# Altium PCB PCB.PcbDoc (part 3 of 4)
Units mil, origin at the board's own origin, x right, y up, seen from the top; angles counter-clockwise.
Board outline 6311.26 x 4737.49 mil, 2 copper layers (Top Layer, Bottom Layer); 252 components, 238 nets, 1140 pads, 635 vias.
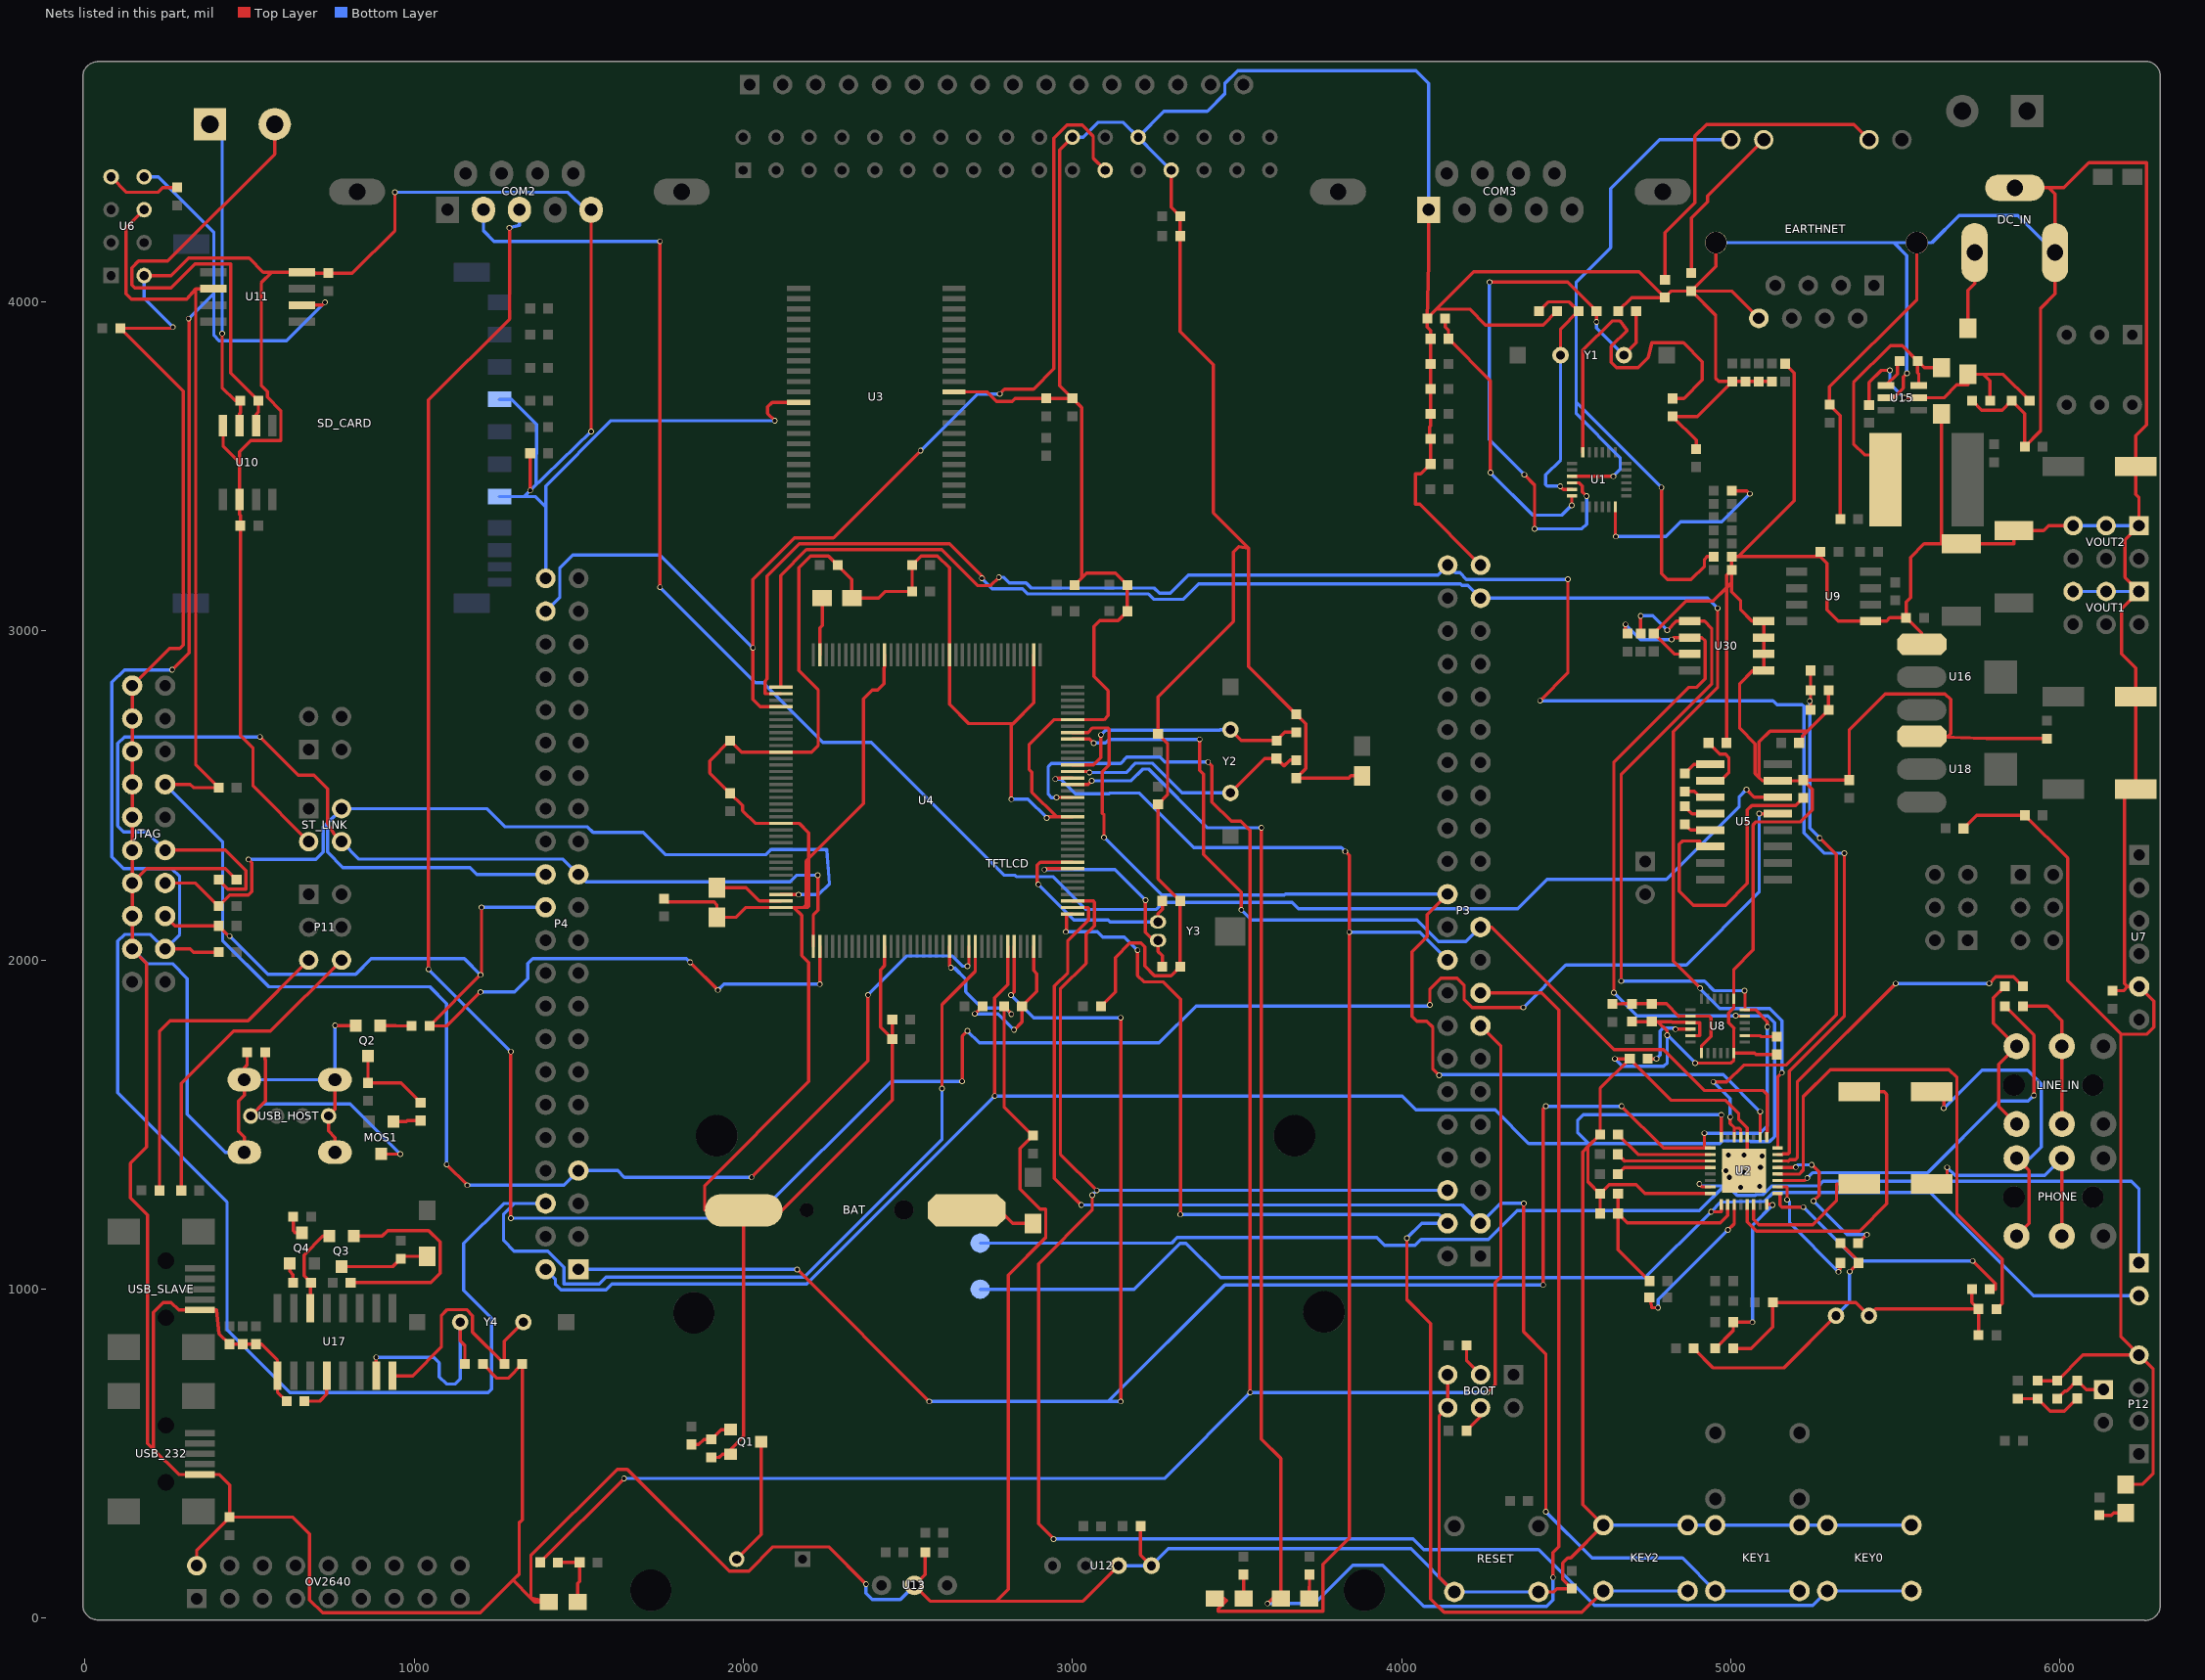
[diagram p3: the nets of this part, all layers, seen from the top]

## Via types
v1: diameter 17, hole 12, Top Layer to Bottom Layer, 622 vias
v2: diameter 25, hole 15, Top Layer to Bottom Layer, 9 vias
v3: diameter 275.59, hole 129.92, Top Layer to Bottom Layer, 4 vias

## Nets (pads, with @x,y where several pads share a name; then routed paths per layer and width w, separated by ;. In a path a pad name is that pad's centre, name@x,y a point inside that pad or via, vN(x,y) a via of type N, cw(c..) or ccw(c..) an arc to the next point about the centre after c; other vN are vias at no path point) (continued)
GND: 94.1 BAT.2 BOOT.5 BOOT.6 C3.1 C5.1 C7.1 C8.1 C11.1 C12.1 C13.1 C14.1 C15.1 C22.1 C23.1 C27.1 C28.1 C29.1 C30.1 C31.1 C32.1 C33.1 C34.1 C35.1 C36.1 C37.1 C38.2 C39.2 C40.2 C41.1 C42.1 C43.2 C44.2 C45.2 C46.1 C47.1 C48.1 C49.1 C50.1 C51.1 C52.1 C53.1 C54.1 C55.1 C56.1 C57.1 C58.1 C59.1 C60.1 C61.1 C62.1 C63.2 C65.2 C66.1 C68.1 C69.1 C70.2 C71.2 C72.1 C73.1 C74.1 C75.2 C76.1 C77.1 C78.2 C79.1 C80.1 C81.2 C82.1 C84.1 C85.2 C86.1 C87.2 C88.2 C89.1 C90.1 C91.1 C92.1 C93.1 C95.1 C96.2 C97.1 C98.1 C99.1 COM2.5 COM3.1 D3.1 D5.1 D6.1 DC_IN.2 DC_IN.3 EARTHNET.8 EARTHNET.13 EARTHNET.14 JTAG.4 JTAG.6 JTAG.8 JTAG.10 JTAG.12 JTAG.14 JTAG.16 JTAG.18 JTAG.20 KEY0.1 KEY1.1 KEY2.1 LS.1 OV2640.2 P3.43 P4.44 P12.4 PWR.2 Q1.1 Q2.1 R8.2 R9.2 R10.1 R11.1 R15.1 R17.1 R18.1 R19.1 R26.2 R36.1 R40.2 R61.1 R67.2 RESET.2 SD_CARD.3 SD_CARD.6 ST_LINK.3 TFTLCD.22 TFTLCD.26 TFTLCD.27 U2.12 U2.24 U2.33 U3.12 U3.34 U4.16 U4.31 U4.38 U4.51 U4.61 U4.83 U4.94 U4.107 U4.120 U4.130 U5.15 U6.1 U7.5 U8.1 U8.9 U8.11 U8.18 U9.5 U10.2 U10.8 U11.4 U12.3 U12.4 U13.2 U15.2 U16.1 U17.1 U18.1 U30.1 U30.2 U30.3 U30.4 U30.7 USB_232.5 USB_HOST.4 USB_HOST.5 USB_HOST.6 USB_HOST.7 USB_HOST.8 USB_SLAVE.5 VOUT1.1 VOUT1.3 VOUT1.5 VOUT2.1 VOUT2.3 VOUT2.5 | length 66976.9
  Top Layer w9.84: 4739.39,1291.1 U2.24@4937.59,1291.1 ; 4821.58,1811.58 4869.1,1811.58 4869.1,1809.84 U8.9@4877.28,1809.84 4906,1809.84 4906,1770.47 U8.11@4877.28,1770.47 ; v1(4891.79,1687.21) 5000.42,1687.21 5009.21,1696 U8.18@5009.21,1717.28 5009.21,1793.79 ; 4993.5,1840 5009.21,1855.71 U8.1@5009.21,1882.72 5009.21,1972 ; 5023.72,1516.28 5049.84,1490.16 U2.12@5049.84,1462.41 U2.33@5049.84,1369.84
  Top Layer w10: U6.1@180,4080 262,4080 315,4133 499.06,4133 542,4090.06 568,4090.06 ; v1(267.56,3923.44) 264.06,3919.94 C70.2@107.5,3919.94 298.5,3728.94 298.5,2957.5 288,2947 257,2947 JTAG.20@144,2834 JTAG.18@144,2734 JTAG.16@144,2634 JTAG.14@144,2534 JTAG.12@144,2434 JTAG.10@144,2334 JTAG.8@144,2234 ; OV2640.2@340,160 340,207.44 C65.2@440.06,307.5 ; U10.8@420,3624.41 420,3562 470,3512 ; R36.1@461,2244 427,2278 188,2278 JTAG.8@144,2234 ; USB_HOST.8@484.41,1416.06 484.41,1462.59 467,1480 467,1572.59 484.41,1590 USB_HOST.7@484.41,1636.54 484.41,1673 493,1681.59 C80.1@493,1720 ; C93.1@613,660 585,688 U17.1@585,737.64 585,785 537,833 C92.1@520,833 C91.1@480,833 C97.1@440,833 408,865 400,937.01 USB_SLAVE.5@349.06,937.01 285,937.01 262.01,960 238.01,960 208,929.99 208,514.01 ; ST_LINK.3@680,2360 511,2529 511,2644 472.5,2682.5 C75.2@472.5,3320.06 472.5,3351.06 470,3353.56 U10.2@470,3400 470,3512 ; USB_HOST.5@760,1416.06 760,1461 740.31,1480.69 USB_HOST.4@740.31,1526.3 760,1545.99 USB_HOST.6@760,1636.54 ; v1(760,1801.26) Q2.1@822.6,1801.26 ; v1(942,4333) 942,4217 812.5,4087.5 C78.2@740.06,4087.5 700.56,4087.5 698,4090.06 U11.4@660,4090.06 568,4090.06 ; C98.1@1209,773 1252.3,729.7 1285.7,729.7 C99.1@1329,773 1329,299.5 1319.5,290 1319.5,134.5 1301,116 ; v1(1353,3427) C72.1@1353,3540 ; v1(1538,3606) COM2.5@1538,4280 ; C57.1@1760,2187 1770.5,2176.5 1911.44,2176.5 1919.94,2168 C45.2@1919.94,2130 1977,2130 2006.66,2159.66 U4.107@2114.53,2159.66 2154.34,2159.66 ; R61.1@1903,489 1927,489 1936.6,498.6 Q1.1@1961.74,498.6 1961.74,514 2001.48,553.74 BAT.2@2001.48,1240 ; v1(2096,3639) 2074,3661 2074,3680.94 2088,3694.94 U3.34@2167.91,3694.94 ; v1(2373,104) 2260,217 2090.62,217 2017,143.38 1957.62,143.38 1648,453 1617,453 1355,191 1355,62 ; U4.120@2429.49,2041.55 2429.49,1982.95 2417.04,1970.5 2417.04,1795.96 C58.1@2453,1760 ; U4.61@2429.49,2927.38 2429.49,2890 2427.67,2888.18 2427.67,2840 2408.67,2821 2392,2821 2365,2794 2365,2475 2198.72,2308.72 ; C59.1@2453,1820 C58.1@2453,1760 ; C82.1@2553,200 2553,133 U13.2@2520,100 2568,52 2769,52 ; U4.130@2626.34,2041.55 2626.34,1981.66 v1(2631,1977) ; U3.12@2640.35,3726.43 2741.63,3726.43 2770,3698.06 2816.73,3698.06 2825.67,3707 C36.1@2920,3707 C37.1@3000,3707 ; v1(2814.44,1835.89) 2814.44,1838.13 R26.2@2792.5,1860.06 2792.5,1554.5 C61.1@2880,1467 2841,1428 2841,1304 2902,1243 2919,1243 2919,1157 2805,1043 2805,88 2769,52 ; v1(2814.5,2489) 2814.5,2713.5 2819.71,2718.71 ; U4.38@2882.24,2927.38 2882.24,2781.24 2819.71,2718.71 ; v1(2922,2432) 2925.25,2435.25 2952,2435.25 ; TFTLCD.22@2999.92,4500.24 2961.58,4461.89 2961.58,3745.42 C37.1@3000,3707 ; U4.16@3000.35,2435.25 2952,2435.25 ; C52.1@3007,3140 3028,3161 ; C60.1@3087,1860 3130.5,1903.5 3130.5,2008 3174,2051.5 3208,2051.5 3219.5,2040 3219.5,1981.5 3249,1952 3299.56,1952 C40.2@3327.5,1979.94 C43.2@3327.5,2179.94 3260,2247.44 C50.1@3260,2473 3289,2502 3289,2658 C49.1@3260,2687 3260,2800.28 3489,3029.28 3489,3240 3505,3256 3535.5,3251.75 ; U12.3@3140,160 3032,52 2769,52 ; C79.1@3207,280 3207,193 U12.4@3240,160 ; TFTLCD.27@3299.92,4400.24 3299.92,4287.51 C38.2@3327.5,4259.94 C39.2@3327.5,4199.94 3327.5,3909.5 3428,3809 3428,3359.25 3535.5,3251.75 ; C62.1@3880.06,2560 3846.46,2560 3839.46,2553 C42.1@3680,2553 3709,2582 3709,2718 C41.1@3680,2747 3535.5,2891.5 3535.5,3251.75 ; COM3.1@4082,4280 4082,4119 C12.1@4078,3950 ; BOOT.5@4140,740 BOOT.6@4140,640 4114,614 4114,126 RESET.2@4160,80 ; P3.43@4240,3200 4054.94,3385.06 4041.5,3385.06 4041.5,3477.06 4057.81,3477.06 C28.1@4088,3507.25 C27.1@4088,3583.38 4085.36,3586.02 4085.36,3621 4088,3623.64 C15.1@4088,3659.5 C14.1@4088,3735.63 C13.1@4088,3811.75 C11.1@4088,3887.88 4088,3913 4078,3923 C12.1@4078,3950 ; RESET.2@4415.91,80 4461,80 4471,90 C48.1@4517,90 4489,118 4489,168 4505,184 4514,184 KEY2.1@4613,283 4550,346 4550,1417 4566,1433 ; C23.1@4472,3972 4430,3930 4255,3930 4207,3978 4106,3978 ; C3.1@4603,1230 C5.1@4603,1290 ; v1(4648,1700) C77.1@4693,1700 ; C22.1@4658,3972 4699,4013 R18.1@4800,4013 ; C73.1@4700,1813 C74.1@4760,1813 4778,1813 ; 4739.39,1291.1 4712.5,1318 4631,1318 C5.1@4603,1290 ; v1(4807,1772) 4807,1784 4778,1813 ; 4821.58,1811.58 4820.16,1813 4778,1813 ; U30.7@4875.59,2930 4828.56,2930 C81.2@4766.06,2992.5 4864.5,3090.94 4945.94,3090.94 4987,3132 ; R10.1@4895,3553 4895,3580 R11.1@4823,3652 4898.94,3652 C33.1@5004.94,3758 ; EARTHNET.14@4954.88,4180 4954.88,4107.88 R19.1@4880,4033 ; C66.1@4987,2660 4987,3132 ; 4993.5,1840 4993.5,1809.5 5009.21,1793.79 ; U8.18@5009.21,1717.28 5072,1717.28 5076.28,1713 C76.1@5140,1713 ; 5009.21,1972 5068,2030.79 5068,2411 5077,2420 5212,2420 5248,2456 5248,2519 C68.1@5220,2547 ; 5023.72,1516.28 5023.72,1534.28 4984,1574 4819,1574 C77.1@4693,1700 ; U2.33@5040,1360 U2.33@5049.84,1369.84 ; EARTHNET.8@5085.2,3950 5002.2,4033 R19.1@4880,4033 ; C30.1@5124.94,3758 C31.1@5084.94,3758 C32.1@5044.94,3758 C33.1@5004.94,3758 ; C29.1@5164.94,3812 5192.87,3784.06 5192.87,3395.87 5022.94,3225.94 ; C63.2@5207.5,2659.94 5217.5,2659.94 5217.5,2680.5 5233,2696 ; R40.2@5272.5,3240.06 5254.5,3225.94 ; C7.1@5297,2820 C8.1@5297,2760 5233,2696 ; C71.2@5332.5,3340.06 5332.5,3655.06 R67.2@5300.06,3687.5 5300.06,3741.89 5565.12,4006.94 EARTHNET.13@5565.12,4180 ; U15.2@5471,3708.6 5494.38,3708.6 5524.11,3738.32 5524.11,3772.11 v1(5535,3783) ; U16.1@5579.94,2959.97 5579.94,2992.63 C87.2@5532.5,3040.06 ; D3.1@5640,3660 5640,3265 ; R17.1@5707,2400 5747,2440 94.1@5893,2440 6023,2310 6023,1937 6185,1775 ; C89.1@5733,3700 5762,3671 5824,3671 C90.1@5853,3700 5893,3660 C84.1@5893,3560 5941,3608 5941,3980 5985,4024 DC_IN.2@5985,4150 5985,4328 5966.15,4346.85 ; DC_IN.3@5862.95,4346.85 5966.15,4346.85 ; C34.1@5932,722 C35.1@5992,722 6070,800 P12.4@6240,800 ; C86.1@5960,2673 5776.97,2673 U18.1@5579.94,2679.97 5659.97,2679.97 5668,2688 5668,2792 5651,2809 5469,2809 5360,2700 C95.1@5360,2547 C68.1@5220,2547 ; VOUT2.5@6040,3320 5965,3320 5950,3305 D6.1@5860,3305 5860,3265 D5.1@5700,3265 5640,3265 ; C69.1@6160,1907 6193,1907 6205.58,1919.58 ; PWR.2@6200.06,407.04 6250.04,407.04 6283,440 6283,757 P12.4@6240,800 ; JTAG.8@144,2234 JTAG.6@144,2134 JTAG.4@144,2034 188,1990 188,1432 138.47,1382.47 138.47,1277.53 190.69,1225.31 190.69,531.32 208,514.01 ; 208,514.01 285,437.01 USB_232.5@349.06,437.01 408,437.01 440.06,404.95 C65.2@440.06,307.5 ; C65.2@440.06,307.5 632,307.5 683,256.5 683,56 722,17 1202,17 1301,116 ; 470,3512 470,3544.91 504,3578.91 595.5,3578.91 595.5,3669.91 555,3710.41 555,3728 536,3747 536,4058.06 568,4090.06 ; 1301,116 1355,62 ; 1355,62 1367.06,49.94 LS.1@1410.03,49.94 1355,62 ; BAT.2@2001.48,1240 1883,1240 1883,1315 2199,1631 2199,1993 2178,2014 2178,2136 2154.34,2159.66 ; BAT.2@2001.48,1240 2118,1240 2453,1575 C58.1@2453,1760 ; 2154.34,2159.66 2182.66,2159.66 ; 2182.66,2159.66 2191,2168 2191,2301 2198.72,2308.72 ; 2182.66,2159.66 2194.35,2159.66 2198.72,2164.03 2198.72,2308.72 ; 2198.72,2308.72 2198.72,2386.65 2169.81,2415.57 U4.94@2114.53,2415.57 2036.04,2415.57 1997.58,2454.02 1997.58,2469.42 C56.1@1960,2507 1898.5,2568.5 1898.5,2605.5 C55.1@1960,2667 1994.9,2632.1 U4.83@2114.53,2632.1 2208,2632.1 2227.56,2651.67 2227.56,2821.44 2169,2880 2169,3192.56 2204.5,3228.06 2258.94,3228.06 C54.1@2287,3200 2330,3157 C44.2@2330,3099.94 2411,3099.94 2431.06,3120 C53.1@2513,3120 C51.1@2513,3200 2541,3228 2590.34,3228 2626.34,3192 U4.51@2626.34,2927.38 2626.34,2777.66 2685.29,2718.71 2819.71,2718.71 ; 2952,2435.25 2876.82,2510.43 2876.82,2570.5 2868.5,2578.82 2868.5,2655.5 2943.53,2730.53 U4.31@3000.35,2730.53 3096,2730.53 3109,2743.53 3109,2818.5 3065.5,2862 3065.5,3014.5 3083,3032 3139,3032 C47.1@3167,3060 C46.1@3167,3140 3131,3176 3043,3176 3028,3161 ; C37.1@3000,3707 3028,3679 3028,3161 ; C12.1@4078,3950 4106,3978 ; 4106,3978 4219,4091 4722,4091 R18.1@4800,4013 ; 4566,1433 4566,1327 C5.1@4603,1290 ; 4566,1433 R15.1@4603,1470 4603,1610 C77.1@4693,1700 ; R18.1@4800,4013 4820,4033 R19.1@4880,4033 ; R19.1@4880,4033 4954,3959 4954,3768 4964,3758 C33.1@5004.94,3758 ; 4987,3132 5002.5,3147.5 ; 4987,3132 4987,3170.44 R9.2@5002.5,3185.94 ; 5002.5,3147.5 R9.2@5002.5,3185.94 ; 5002.5,3147.5 5002.5,3119 5030,3091.5 5030,3064 5064,3030 U30.4@5100,3030 U30.3@5100,2980 U30.2@5100,2930 U30.1@5100,2880 5067,2880 5027,2840 5027,2704 5074,2657 5074,2567 5086,2555 ; R9.2@5002.5,3185.94 R8.2@5002.5,3225.94 5022.94,3225.94 ; 5022.94,3225.94 5254.5,3225.94 ; 5086,2555 5086,2663 5119,2696 5233,2696 ; 5086,2555 5096,2545 U5.15@5142.36,2545 5218,2545 C68.1@5220,2547 ; 5254.5,3225.94 5272.06,3225.94 5292,3206 5292,3064 5326,3030 U9.5@5424.41,3030 5473,3030 5483.06,3040.06 C87.2@5532.5,3040.06 ; C87.2@5532.5,3040.06 5532.5,3087.94 5546.06,3101.5 5546.06,3224 5587.06,3265 5640,3265 ; 5966.15,4346.85 6012,4346.85 6088.15,4423 6263,4423 6263,3626 6230.24,3593.24 C85.2@6230.24,3500 6230.24,3414.76 6240,3405 VOUT2.1@6240,3320 6197,3277 6197,3163 VOUT1.1@6240,3120 6187,3067 6187,2931 6230.24,2887.76 C88.2@6230.24,2800 C96.2@6230.24,2520 6196,2520 6196,1928 6204.42,1919.58 6205.58,1919.58 ; 6185,1775 6185,855 P12.4@6240,800 ; 6185,1775 6264,1775 6285,1796 6285,1875 U7.5@6240.43,1919.58 6205.58,1919.58
  Bottom Layer w10: JTAG.4@144,2034 189,1989 266,1989 311,1944 311,1532.06 427,1416.06 USB_HOST.8@484.41,1416.06 ; U6.1@180,4080 180,4011 v1(267.56,3923.44) ; USB_HOST.7@484.41,1636.54 USB_HOST.6@760,1636.54 v1(760,1801.26) ; v1(942,4333) 1468,4333 1521,4280 COM2.5@1538,4280 ; SD_CARD.6@1259.64,3408.54 1334.54,3408.54 ; SD_CARD.3@1259.64,3703.82 1296,3703.82 1372,3627.82 1370.54,3444.54 v1(1353,3427) 1334.54,3408.54 ; P4.44@1400,3160 1400,3376.54 ; v1(1538,3606) 1353.27,3426.72 1334.54,3408.54 ; v1(2096,3639) 1598.46,3639 1400,3440.54 1400,3376.54 ; v1(2373,104) 2373,76 2391.53,57.47 2477.47,57.47 U13.2@2520,100 ; v1(2631,1977) 2641,1977 2675.5,1942.5 2675.5,1904 2725.08,1854.42 2795.91,1854.42 v1(2814.44,1835.89) ; v1(2814.5,2489) 2865,2489 v1(2922,2432) ; TFTLCD.22@2999.92,4500.24 3032.24,4500.24 3077.47,4545.47 3154.69,4545.47 TFTLCD.26@3199.92,4500.24 ; U12.3@3140,160 U12.4@3240,160 3291.61,211.61 4028.39,211.61 RESET.2@4160,80 RESET.2@4415.91,80 ; TFTLCD.27@3299.92,4400.24 3299,4400.24 3255.94,4443.3 3255.94,4444.22 TFTLCD.26@3199.92,4500.24 ; COM3.1@4082,4280 4082,4664 4043,4703 3502,4703 3463,4664 3463,4632 3409.71,4578.71 3278.4,4578.71 TFTLCD.26@3199.92,4500.24 ; KEY2.1@4613,283 KEY2.1@4868.91,283 KEY1.1@4953,283 KEY1.1@5208.91,283 KEY0.1@5293,283 KEY0.1@5548.91,283 ; v1(4648,1700) 4671,1677 4796,1677 4807,1688 v1(4807,1772) v1(4891.79,1687.21) ; EARTHNET.14@4954.88,4180 5496,4180 ; v1(5535,3783) 5535,4141 5496,4180 ; DC_IN.2@5985,4150 5872,4263 5694,4263 5611,4180 EARTHNET.13@5565.12,4180 5496,4180 ; VOUT1.5@6040,3120 VOUT1.3@6140,3120 VOUT1.1@6240,3120 ; VOUT2.5@6040,3320 VOUT2.3@6140,3320 VOUT2.1@6240,3320 ; 1334.54,3408.54 1368,3408.54 1400,3376.54
  other v2: 5030,1310 5087.24,1312.76 4995,1340 5040,1355 4985,1360 5090,1370 5095,1405 4992.76,1407.24 5040,1407.24
I2S_LRCK: P3.44 U2.7 U4.73 | length 5654.7
  Top Layer w9.84: U2.7@5142.41,1409.21 5157.13,1409.21 5158.85,1410.92 5174.71,1410.92
  Top Layer w10: U4.73@2114.53,2828.95 2114,2828.95 2114,3169 2192,3247 2603,3247 2712,3138 2751.89,3138 v1(2776.89,3163) ; v1(4421,2788) 4505,2872 v1(4505,3157) ; 5174.71,1410.92 5178,1414.21 5178,1663 5345,1830 v1(5345,2325)
  Bottom Layer w10: v1(2776.89,3163) 2791.5,3163 2808,3146.5 2859.5,3146.5 2875.5,3130.5 3248.91,3130.5 3264.41,3115 3297,3115 3352,3170 4110,3170 P3.44@4140,3200 4163,3177 4177,3177 4197,3157 v1(4505,3157) ; v1(4421,2788) 5128,2788 5140,2776 5217,2776 5222,2771 5222,2386.5 5283.5,2325 v1(5345,2325)
I2S_SCLK: P3.41 U2.8 U4.74 | length 5397
  Top Layer w9.84: U2.8@5142.41,1428.9 5143,1428.9 5143,1646
  Top Layer w10: U4.74@2114.53,2809.27 2066.09,2809.27 2066.09,2847.65 2072.57,2854.12 2072.57,3167.57 2170,3265 2626.76,3265 2728.3,3163.45 2731.61,3160.15 v1(2725,3160.15) ; v1(4907,1915) 4825.5,1996.5 4825.5,2694.41 4960,2828.91 v1(4960,3069) ; 5143,1646 v1(5155,1658)
  Bottom Layer w10: v1(2725,3160.15) 2756.65,3128.5 2849,3128.5 2865,3112.5 3231.22,3112.5 3247.22,3096.5 3337.5,3096.5 3384,3143 4179,3143 4183,3139 4201,3139 P3.41@4240,3100 4929,3100 v1(4960,3069) ; v1(4907,1915) 4907,1912 4966,1853 5118,1853 5155,1816 v1(5155,1658)
I2S_SDIN: P3.24 U2.10 U4.29 | length 3322.3
  Top Layer w9.84: U2.10@5089.21,1462.41 v1(5089.21,1539.54)
  Top Layer w10: U4.29@3000.35,2691.16 3047.16,2691.16 3061.5,2705.5 3107.65,2705.5 3111.65,2701.5 3111.65,2592.65 3091,2572 3091,2446 3096,2441 v1(3096,2373) ; v1(4114,1650) 4095,1669 4095,1795.6 4075.93,1814.67 4045.83,1814.67 4031.6,1828.9 4031.6,2025.23 4077.58,2071.21 4077.58,2138.43 P3.24@4139.58,2200.43
  Bottom Layer w10: v1(3096,2373) 3271.5,2197.5 3644.25,2197.5 3647.18,2200.43 P3.24@4139.58,2200.43 ; v1(4114,1650) 4116.16,1652.16 4976.59,1652.16 v1(5089.21,1539.54)
I2S_SDOUT: P3.21 U2.9 U4.28 | length 2962.3
  Top Layer w9.84: U2.9@5108.9,1462.41 5108.9,1475 5111,1477.1 5111,1591.07
  Top Layer w10: U4.28@3000.35,2671.47 3052.68,2671.47 v1(3064.66,2659.5) ; v1(3386.5,2670.5) 3386.5,2576.36 3398.36,2564.5 3398.36,2321.34 3513,2206.71 v1(3513,2153) ; P3.21@4239.58,2100.43 4272.57,2100.43 4645,1728 4795.5,1728 4919.5,1604 5098.07,1604 5111,1591.07
  Bottom Layer w10: v1(3064.66,2659.5) 3100.5,2659.5 3111.5,2670.5 v1(3386.5,2670.5) ; v1(3513,2153) 3544,2122 4046,2122 4111.63,2056.37 4195.52,2056.37 P3.21@4239.58,2100.43
IIC_SCL: P4.2 R62.1 U2.16 U4.139 U8.23 U30.6 | length 7543.5
  Top Layer w9.84: U2.16@4971.1,1462.41 v1(4971.1,1530) ; v1(5015,1831) 5016.47,1829.53 U8.23@5042.72,1829.53
  Top Layer w10: v1(2764,1587) 2764,1885.78 2803.5,1925.29 U4.139@2803.5,2041.55 ; v1(4645,1901) 4645,2601.59 4872,2828.59 4895.59,2828.59 4922,2855 4922,2970 4912,2980 U30.6@4875.59,2980 4826.03,2980 v1(4820,2973.97) ; v1(4680,3020) 4680,2998 R62.1@4686,2992
  Bottom Layer w10: P4.2@1399.58,1060.43 1429.36,1030.64 1429.36,1016 1446.94,998.43 1583.93,998.43 1601.5,1016 2193,1016 v1(2764,1587) 4002,1587 4044,1545 4284,1545 4386,1443 4568,1443 ; v1(4645,1901) 4715,1831 v1(5015,1831) 5112,1831 5133,1810 5133,1464 5117.5,1448.5 5076.98,1448.5 5076.48,1448 5060.76,1448 5058.02,1450.74 4974.74,1450.74 4966.99,1443 4568,1443 ; v1(4680,3020) 4726.03,2973.97 v1(4820,2973.97) ; v1(4971.1,1530) 4552,1530 4534.62,1512.62 4534.62,1476.38 4568,1443
IIC_SDA: P4.1 R65.1 U2.17 U4.140 U8.24 U30.5 | length 9207.4
  Top Layer w9.84: 4795.1,1428.9 4919.77,1428.9 ; v1(4919.77,1474.08) 4919.77,1428.9 ; v1@5043,1906 U8.24@5043,1849.21 ; 5074.79,1849.21 U8.24@5043,1849.21 ; 4919.77,1428.9 U2.17@4937.59,1428.9 4919.77,1428.9 ; U8.24@5043,1849.21 U8.24@5042.72,1849.21 U8.24@5043,1849.21
  Top Layer w10: v1(2164,1060) v1(2565,659) ; v1(2813.38,1893.92) 2823.19,1903.73 U4.140@2823.19,2041.55 ; v1(3147,659) v1(3147,1825) ; v1(4430,1013) 4430,1548 v1(4438,1556) ; v1(4667,1936.5) 4667,2562.97 4942,2837.97 4942,3008 4920,3030 U30.5@4875.59,3030 4835,3030 v1(4807,3002) ; v1(4668,1556) 4795.1,1428.9 ; R65.1@4726,2992 v1(4726,3046) ; v1(5042,1907) v1@5043,1906 ; 5074.79,1849.21 5111,1813 v1(5111,1797)
  Bottom Layer w10: P4.1@1499.58,1060.43 2163.57,1060.43 v1(2164,1060) ; v1(2813.38,1893.92) 2882.3,1825 v1(3147,1825) ; v1(3147,659) 3109,659 ; v1(4430,1013) 3463,1013 3109,659 ; v1(4438,1556) v1(4668,1556) ; v1(4667,1936.5) 4920,1936.5 4949.5,1907 v1(5042,1907) ; v1(4726,3046) 4763,3046 v1(4807,3002) ; v1(4919.77,1474.08) 5089.08,1474.08 5111,1496 v1(5111,1797) ; 3109,659 v1(2565,659) 3109,659
JTCK: JTAG.9 P4.25 R36.2 ST_LINK.4 U4.109 | length 3459.1
  Top Layer w10: JTAG.9@244,2334 427,2334 489,2272 489,2216 434.56,2216 R36.2@406.5,2244.06 ; v1(532,2678) 648,2562 696,2562 737.47,2520.53 737.47,2417 757,2383 ST_LINK.4@780,2360 ; U4.109@2212.95,2041.55 2212.95,2137.62 2226.5,2151.16 v1(2226.5,2258.09)
  Bottom Layer w10: JTAG.9@244,2334 188,2390 118,2390 100,2408 100,2658 120,2678 v1(532,2678) ; ST_LINK.4@780,2360 833.07,2306.93 1453.08,2306.93 P4.25@1499.58,2260.43 1521.86,2238.14 2142.79,2238.14 2162.73,2258.09 v1(2226.5,2258.09)
JTDI: JTAG.5 P4.24 R29.2 R57.1 U4.110 | length 3369.2
  Top Layer w10: JTAG.5@244,2134 273.94,2104.06 R29.2@406.5,2104.06 437.56,2073 v1(440,2073) ; v1(1202,1903) 1099,1800 R57.1@1047,1800 ; v1(1205,2160.43) 1205,1958 v1(1202,1955) ; v1(1839,1993) v1(1923,1909) ; v1(2232.64,1927) U4.110@2232.64,2041.55 ; R57.1@1047,1800 v1(1202,1955) ; R57.1@1047,1800 v1(1202,1955)
  Bottom Layer w10: v1(440,2073) 556,1957 823,1957 870,2004 1153,2004 v1(1202,1955) ; v1(1202,1903) 1305,1903 1346,1944 1346,1989.43 1361,2004.43 1827.57,2004.43 v1(1839,1993) ; v1(1205,2160.43) P4.24@1399.58,2160.43 ; v1(1923,1909) 1941,1927 v1(2232.64,1927)
JTDO: JTAG.13 P4.7 R33.2 U4.133 U6.5 U11.6 | length 6177.7
  Top Layer w10: U6.5@180,4280 125,4225 125,4024 141,4008 309,4008 337,4040 ; JTAG.13@244,2534 320,2534 329.94,2524.06 R33.2@406.5,2524.06 337,2593.56 337,4040 ; U11.6@390,4040 337,4040 ; v1(1099,1379) v1(1162,1316) ; v1(2025,1340) 2379,1694 v1(2379,1894.28) ; v1(2681.32,1981.58) 2685.39,1985.65 U4.133@2685.39,2041.55
  Bottom Layer w10: JTAG.13@244,2534 418.5,2359.5 418.5,2059.5 559,1919 1048,1919 1099,1868 v1(1099,1379) ; v1(1162,1316) 1455.15,1316 P4.7@1499.58,1360.43 1618.57,1360.43 1639,1340 v1(2025,1340) ; v1(2379,1894.28) 2497.46,2012.74 2634.47,2012.74 2665.62,1981.58 v1(2681.32,1981.58)
JTMS: JTAG.7 P4.26 R30.2 ST_LINK.2 U4.105 | length 3447.6
  Top Layer w10: JTAG.7@244,2234 336.56,2234 R30.2@406.5,2164.06 440.44,2198 497,2198 507,2208 507,2296 v1(497,2306) ; U4.105@2114.53,2199.03 v1(2168.06,2199.03)
  Bottom Layer w10: v1(497,2306) 702,2306 724,2328 724,2404 737,2417 ; P4.26@1399.58,2260.43 1190.57,2260.43 1170,2281 784,2281 737,2328 737,2417 ; v1(2168.06,2199.03) 2229.03,2199.03 2262,2232 2254,2336 2085,2336 2069.5,2320.5 1763.5,2320.5 1696,2388 1544,2388 1527,2405 1277,2405 1222,2460 ST_LINK.2@780,2460 ; 737,2417 ST_LINK.2@780,2460 ; 737,2417 ST_LINK.2@780,2460
JTRST: JTAG.3 P4.6 R28.2 U4.134 U6.7 U11.2 | length 9407.9
  Top Layer w10: JTAG.3@244,2034 320,2034 329.94,2024.06 R28.2@406.5,2024.06 ; v1(265,2882) 316.5,2933.5 316.5,3947.5 v1(315,3949) ; U11.2@660,3990.06 721.06,3990.06 v1(730,3999) ; v1(2604,1610) 2604,1865.46 2705.08,1966.54 U4.134@2705.08,2041.55
  Bottom Layer w10: U6.7@180,4380 223,4380 392,4211 ; v1(265,2882) 120,2882 82,2844 82,2314 118,2278 264,2278 288,2254 288,2078 JTAG.3@244,2034 200,2078 120,2078 100,2058 100,1597 432,1265 432,877 623,686 1225,686 1235,696 1235,912 1151,996 1151,1139.43 1272,1260.43 1304,1260.43 ; v1(315,3949) 392,4026 ; v1(730,3999) 613,3882 408,3882 392,3898 392,4026 ; v1(2604,1610) 2604,1456.09 2184.91,1037 1583,1037 1562.43,1016.43 1455.58,1016.43 1455.58,1066.65 1406.23,1116 1304,1116 1272,1148 1272,1228.43 1304,1260.43 ; 392,4026 392,4211 ; 392,4026 392,4211 ; 1304,1260.43 P4.6@1399.58,1260.43 1304,1260.43
KEY0: KEY0.2 P3.6 U4.3 | length 5957.9
  Top Layer w10: v1(2943,241) 2897,287 2897,1077 3060,1240 v1(3060,1286) ; U4.3@3000.35,2179.35 3063.42,2179.35 3066.79,2175.98 3066.79,2103.97 3041.71,2078.9 3041.71,1990.27 2963.5,1912.05 2963.5,1410.5 v1(3074,1300)
  Bottom Layer w10: v1(2943,241) 4035,241 4067,209 4416,209 4586,39 5249,39 KEY0.2@5293,83 KEY0.2@5548.91,83 ; v1(3060,1286) v1(3074,1300) ; P3.6@4139.58,1300.43 v1@3074.43,1300.43 ; v1(3074,1300) v1@3074.43,1300.43 ; v1(3074,1300) v1@3074.43,1300.43
KEY1: KEY1.2 P3.3 U4.2 | length 4255.2
  Top Layer w10: U4.2@3000.35,2159.66 3047.11,2159.66 3048.79,2157.98 3048.79,2121.97 2986,2059.18 2986,1962 2945.5,1921.5 2945.5,1337.5 v1(3027,1256) ; v1(4371,1261) 4371,871 4438,804 v1(4438,324)
  Bottom Layer w10: v1(3027,1256) 4184,1256 P3.3@4239.58,1200.43 4300.15,1261 v1(4371,1261) ; v1(4438,324) 4579,183 4853,183 KEY1.2@4953,83 KEY1.2@5208.91,83
KEY2: KEY2.2 P3.4 U4.1 | length 4120.8
  Top Layer w10: v1(2980,2086) 2982,2088 2982,2139.98 U4.1@3000.35,2139.98 ; v1(3198,2030) 3198,1953 3217,1934 3275,1934 3328,1881 v1(3328,1227) ; v1(4016,1155) 4016,968 4088,896 4088,59 4129,18 4548,18 KEY2.2@4613,83
  Bottom Layer w10: v1(2980,2086) 3076,2086 3092,2070 3158,2070 v1(3198,2030) ; v1(3328,1227) 4113,1227 P3.4@4139.58,1200.43 4061.43,1200.43 v1(4016,1155) ; KEY2.2@4613,83 KEY2.2@4868.91,83
LCD_BL: P4.42 TFTLCD.23 U4.76 | length 3633.6
  Top Layer w10: U4.76@2114.53,2769.9 2051.6,2769.9 2029.5,2792 ; v1(2539,3548) 2274,3283 2155.58,3283 2029.5,3156.92 v1(2029.5,2948.5) ; v1(2779,3720) 2794,3735 2882,3735 2943.58,3796.58 2943.58,4497.58 2983,4537 3030,4537 3063,4504 3063,4437.16 TFTLCD.23@3099.92,4400.24 ; 2029.5,2792 v1(2029.5,2948.5) ; 2029.5,2792 v1(2029.5,2948.5)
  Bottom Layer w10: P4.42@1400,3060 1443,3103 1443,3192 1482,3231 1747,3231 v1(2029.5,2948.5) ; v1(2539,3548) 2711,3720 v1(2779,3720)
LED0: D0.2 P3.17 U4.21 | length 6114.5
  Top Layer w10: U4.21@3000.35,2533.68 3047.68,2533.68 v1(3059,2545) ; v1(3574,2402) 3574,545 3632.96,486.04 D0.2@3632.96,60.06 3608.06,60.06 v1(3593,45) ; P3.17@4239.58,1900.43 4425.9,1900.43 4477.91,1848.42 4477.91,218 4460,200.09 v1(4460,124)
  Bottom Layer w10: v1(3059,2545) 3178.5,2545 3214,2580.5 3232,2580.5 3410.5,2402 v1(3574,2402) ; v1(3593,45) 3736,45 3852.19,161.19 3942.81,161.19 4068,36 4440,36 4460,56 v1(4460,124)
LED1: D1.2 P3.20 U4.22 | length 4105.3
  Top Layer w10: v1(2948,2550) 2951.36,2553.36 U4.22@3000.35,2553.36 ; D1.2@3432.96,60.06 3461.5,60.06 3468,53.56 3453.73,39.29 3443,28.56 3443,22 3761,22 3761,164 3841,244 v1(3841,2085) 3841,2318 v1(3829,2330)
  Bottom Layer w10: v1(2948,2550) 2964,2550 3009,2505 3111,2505 3113.5,2507.5 3203.5,2507.5 3369,2342 3817,2342 v1(3829,2330) ; v1(3841,2085) 4055,2085 P3.20@4139.58,2000.43
LIGHT_SENSOR: P3.15 R60.1 U4.19 | length 6899.8
  Top Layer w10: R60.1@1383,170 v1(1638,425) ; v1(2951.69,2494) 2952,2494.31 U4.19@3000.35,2494.31 ; v1(3412,2602) 3424,2590 3424,2480.54 3482.54,2422 3512,2422 3540,2394 v1(3540,686) ; P3.15@4239.58,1800.43 4301.58,1738.43 4301.58,1038.43 4284,1020.85 4284,710 v1(4260,686)
  Bottom Layer w10: v1(1638,425) 3279,425 v1(3540,686) v1(4260,686) ; v1(2951.69,2494) 2936.5,2494 2926.5,2504 2926.5,2588 2936,2597.5 3146.5,2597.5 3165.5,2616.5 3266,2616.5 3280.5,2602 v1(3412,2602)
LINGHT_SENSOR: 
LINK_LED: EARTHNET.12 R8.1 U1.3 | length 2734.9
  Top Layer w9.84: U1.3@4517.28,3469.84 v1@4642.84,3469.84
  Top Layer w10: v1@4642.84,3469.84 v1(4643,3470) ; v1(4789.5,3436) 4789.5,3174.5 4808,3156 4879.46,3156 4920,3196.54 4920,3218 4928,3226 R8.1@4948,3226
  Bottom Layer w10: v1(4643,3470) 4664,3491 4664,3527 4530.5,3660.5 4530.5,3695 ; v1(4789.5,3436) 4530.5,3695 ; EARTHNET.12@5000.16,4492.91 4783.91,4492.91 4635,4344 4635,4165 4530.5,4060.5 ; 4530.5,3695 4530.5,4060.5 ; 4530.5,3695 4530.5,4060.5
NetBAT_1: BAT.1 D2.1 | length 217.9
  Top Layer w10: BAT.1@2678.65,1240 2778,1240 2818,1200 D2.1@2880,1200
NetBEEP_2: BEEP.2 Q1.3 | length 386.8
  Top Layer w10: BEEP.2@1980,180 2054.26,254.26 Q1.3@2054.26,536
NetBOOT_3: BOOT.3 R34.2 | length 107.5
  Top Layer w10: R34.2@4197.5,829.94 4197.5,782.5 BOOT.3@4240,740
NetBOOT_4: BOOT.4 R35.1 | length 87.8
  Top Layer w10: R35.1@4197,570 4240,613 BOOT.4@4240,640
NetC3_2: C3.2 C5.2 R1.1 U2.26 | length 692.2
  Top Layer w9.84: 4990.79,1224 U2.26@4990.79,1257.59
  Top Layer w10: C5.2@4657.5,1289.94 C3.2@4657.5,1229.94 ; R1.1@4753,1025 4657.5,1120.5 C3.2@4657.5,1229.94 ; 4990.79,1224 4968.58,1201.79 4685.65,1201.79 C3.2@4657.5,1229.94
NetC4_1: C4.1 U2.29 | length 942.5
  Top Layer w9.84: 5049.84,1205.24 U2.29@5049.84,1257.59
  Top Layer w10: 5049.84,1205.24 5078.42,1176.66 5391.19,1176.66 5474,1259.47 5474,1592 5466,1600 C4.1@5390,1600
NetC4_2: C4.2 PHONE.1 | length 996.7
  Top Layer w10: C4.2@5610.24,1600 5647,1600 v1(5647,1550) ; PHONE.1@5868.11,1161.89 5906,1199.78 5906,1360.22 PHONE.1@5868.11,1398.11
  Bottom Layer w10: v1(5647,1550) 5763,1666 5901,1666 5943,1624 5943,1432 5909.11,1398.11 PHONE.1@5868.11,1398.11
NetC6_1: C6.1 U2.30 | length 454.8
  Top Layer w9.84: 5069.53,1211.47 U2.30@5069.53,1257.59
  Top Layer w10: 5069.53,1211.47 5085,1196 5249,1196 5321,1268 5321,1320 C6.1@5390,1320
NetC6_2: C6.2 PHONE.2 | length 713.6
  Top Layer w10: C6.2@5610.24,1320 5657,1320 v1(5657,1370) ; PHONE.2@6005.91,1161.89 PHONE.2@6005.91,1398.11
  Bottom Layer w10: v1(5657,1370) 5681.26,1345.74 5953.53,1345.74 PHONE.2@6005.91,1398.11
NetC7_2: C7.2 C8.2 R7.2 U2.13 U2.14 | length 1798
  Top Layer w9.84: 4998,1503.47 5010.47,1491 ; U2.14@5010.47,1462.41 5010.47,1489.53 5025.24,1489.53 5030,1484.77 U2.13@5030,1462.41
  Top Layer w10: v1(4947,1630) 4988,1630 5039,1681 5168,1681 5320,1833 5320,2321 v1(5270,2371) ; 4998,1503.47 v1(4998,1523) ; C8.2@5242.5,2760.06 v1@5242.5,2784.5 ; v1@5242.5,2787 C7.2@5242.5,2820.06 R7.2@5242.5,2880.06
  Bottom Layer w10: v1(4947,1630) 4998,1579 v1(4998,1523) ; v1(5240,2787) 5240,2401 v1(5270,2371)
NetC9_1: C9.1 U2.3 | length 1193.1
  Top Layer w9.84: U2.3@5142.41,1330.47 5224.68,1330.47
  Top Layer w10: 5224.68,1330.47 v1(5232.4,1338.2) ; C9.1@5833,1860 5921,1772 v1(5921,1589)
  Bottom Layer w10: v1(5232.4,1338.2) 5248.25,1354.04 5597.68,1354.04 5815.44,1571.8 5903.8,1571.8 v1(5921,1589)
NetC9_2: C9.2 LINE_IN.2 | length 450.7
  Top Layer w10: C9.2@5887.5,1859.94 5961.97,1859.94 6005.91,1816 LINE_IN.2@6005.91,1738.11 LINE_IN.2@6005.91,1501.89
NetC10_1: C10.1 U2.6 | length 1123.7
  Top Layer w9.84: U2.6@5142.41,1389.53 5174.98,1389.53
  Top Layer w10: 5174.98,1389.53 5178.85,1393.4 5196.4,1393.4 5202.1,1399.1 5202.1,1630.1 v1(5501,1929) ; v1(5785,1929) 5805,1949 5858,1949 C10.1@5887,1920
  Bottom Layer w10: v1(5501,1929) v1(5785,1929)
NetC10_2: C10.2 LINE_IN.1 | length 506.5
  Top Layer w10: C10.2@5832.5,1920.06 5797.74,1885.3 5797.74,1808.48 LINE_IN.1@5868.11,1738.11 5814,1684 5814,1556 LINE_IN.1@5868.11,1501.89
NetC11_2: C11.2 C12.2 U1.6 | length 867.8
  Top Layer w9.84: v1(4517,3382) 4517,3410.79 U1.6@4517.28,3410.79
  Top Layer w10: C12.2@4132.5,3949.94 4132.5,3923 4142.5,3913 C11.2@4142.5,3887.81 4270,3760.31 v1(4270,3481)
  Bottom Layer w10: v1(4270,3481) 4399,3352 4487,3352 v1(4517,3382)
NetC16_1: C16.1 U2.1 | length 828.6
  Top Layer w9.84: U2.1@5142.41,1291.1 5149.08,1291.1 5149.08,1255.92
  Top Layer w10: 5149.08,1255.92 5155.5,1249.5 v1(5220.5,1249.5) ; v1(5735,1086) 5803.18,1017.82 5803.18,1000 C16.1@5787,1000
  Bottom Layer w10: v1(5220.5,1249.5) 5384,1086 v1(5735,1086)
NetC16_2: C16.2 C18.2 C26.2 MIC.1 R14.2 R16.2 | length 1020
  Top Layer w10: R14.2@5007.5,819.94 5062,819.94 5127.5,885.44 C26.2@5127.5,959.94 5379.35,959.94 MIC.1@5419.58,919.71 5439.93,940.06 C18.2@5752.5,940.06 ; C16.2@5732.5,1000.06 5732.5,960.06 C18.2@5752.5,940.06 ; R16.2@5752.5,860.06 C18.2@5752.5,940.06
NetC17_1: C17.1 U2.2 | length 380.5
  Top Layer w9.84: U2.2@5142.41,1310.79 5171.08,1310.79 v1(5171.08,1271.92)
  Top Layer w10: v1(5327,1053) 5327,1056 5333,1062 C17.1@5333,1080
  Bottom Layer w10: v1(5171.08,1271.92) 5178.6,1264.4 5178.6,1201.4 v1(5327,1053)
NetC17_2: C17.2 C19.2 MIC.2 R13.2 | length 795.6
  Top Layer w10: R13.2@4887.5,819.94 4946.44,761 5160.87,761 MIC.2@5319.58,919.71 ; C19.2@5332.5,1140.06 5390.06,1082.5 C17.2@5387.5,1079.94 v1(5361,1053.44)
  Bottom Layer w10: MIC.2@5319.58,919.71 5361,961.13 v1(5361,1053.44)
NetC18_1: C18.1 U2.4 | length 1584.3
  Top Layer w9.84: U2.4@5142.41,1350.16 5148.48,1350.16 5148.48,1349.58 5208,1349.58
  Top Layer w10: 5208,1349.58 5220.1,1361.68 5220.1,1585.1 5302,1667 5663,1667 5687,1643 5687,1228.52 5824,1091.52 5824,957 C18.1@5807,940
NetC19_1: C19.1 U2.5 | length 474.1
  Top Layer w9.84: U2.5@5142.41,1369.84 v1@5196,1369.84
  Top Layer w10: v1@5196,1369.84 v1(5197.16,1371) ; v1(5246,1378) 5268,1356 5268,1285 v1(5251,1268) ; C19.1@5387,1140 v1(5413,1166)
  Bottom Layer w10: v1(5197.16,1371) 5204.16,1378 v1(5246,1378) ; v1(5251,1268) 5353,1166 v1(5413,1166)
NetC20_1: C20.1 U2.19 | length 289.1
  Top Layer w9.84: 4677.47,1389.53 U2.19@4937.59,1389.53
  Top Layer w10: C20.1@4657,1410 4677.47,1389.53
NetC21_1: C21.1 U2.20 | length 288.8
  Top Layer w9.84: 4676.84,1369.84 U2.20@4937.59,1369.84
  Top Layer w10: C21.1@4657,1350 4676.84,1369.84
NetC22_2: C22.2 R12.1 U1.4 Y1.1 | length 1806.1
  Top Layer w9.84: U1.4@4517.28,3450.16 4538.84,3450.16 4549,3440
  Top Layer w10: v1(4267,4060) 4504,4060 R12.1@4592,3972 v1(4592,3939) ; v1(4373,3475) 4404,3444 v1(4404,3310.55) ; 4549,3440 4549,3423 v1(4562,3410) ; Y1.1@4675,3838 4712.5,3875.5 C22.2@4712.5,3971.94
  Bottom Layer w10: v1(4267,4060) 4267,3581 v1(4373,3475) ; v1(4404,3310.55) 4548,3310.55 4562,3324.55 v1(4562,3410) ; v1(4592,3939) 4592,3921 Y1.1@4675,3838
NetC23_2: C23.2 R12.2 U1.5 Y1.2 | length 797.4
  Top Layer w9.84: v1(4482,3440) 4491.53,3430.47 U1.5@4517.28,3430.47
  Top Layer w10: C23.2@4417.5,3972.06 4445.44,4000 4509.56,4000 R12.2@4537.5,3972.06 4482.87,3917.44 Y1.2@4482.87,3838
  Bottom Layer w10: v1(4482,3440) 4442.5,3440 4437.5,3445 4437.5,3474.5 4482.87,3519.87 Y1.2@4482.87,3838
NetC24_2: C24.2 U2.27 | length 460
  Top Layer w9.84: 5010.47,1199.47 U2.27@5010.47,1257.59
  Top Layer w10: C24.2@4752.5,975.06 4760.5,944 v1(4779,944) ; v1(4991,1180) 5010.47,1199.47
  Bottom Layer w10: v1(4779,944) 4779,968 v1(4991,1180)
NetC25_2: C25.2 R14.1 U2.32 | length 561.6
  Top Layer w9.84: U2.32@5108.9,1257.59 5108.9,1258 5125,1258 v1(5127,1256)
  Top Layer w10: R14.1@4953,820 5007.5,874.5 C25.2@5007.5,899.94 v1(5065.94,899.94)
  Bottom Layer w10: v1(5065.94,899.94) 5065.94,1194.94 v1(5127,1256)
NetC34_2: C34.2 R20.2 R21.1 | length 212.2
  Top Layer w10: R20.2@5871.94,667.5 C34.2@5931.94,667.5 5970.44,629 6013,629 R21.1@6052,668
NetC35_2: C35.2 P2.1 R21.2 | length 174.2
  Top Layer w10: C35.2@5991.94,667.5 6014.87,690.44 6020,690.44 R21.2@6052.06,722.5 6079.56,695 P2.1@6132,695
NetC40_1: C40.1 U4.8 Y3.1 | length 663
  Top Layer w10: v1(2915,2275) 2917.77,2277.77 U4.8@3000.35,2277.77 ; v1(3222,2182.43) 3222,2085 3247,2060 Y3.1@3260,2060 3260,2026 3273,2013 C40.1@3273,1980
  Bottom Layer w10: v1(2915,2275) 3129.43,2275 v1(3222,2182.43)
NetC41_2: C41.2 R23.1 U4.24 Y2.1 | length 788.5
  Top Layer w10: U4.24@3000.35,2592.73 3064,2592.73 3086.47,2615.2 v1(3086.47,2684) ; Y2.1@3480,2700 3513,2667 R23.1@3620,2667 3645.5,2692.5 C41.2@3679.94,2692.5
  Bottom Layer w10: v1(3086.47,2684) 3100.97,2698.5 3447.5,2698.5 3449,2700 Y2.1@3480,2700
NetC42_2: C42.2 R23.2 U4.23 Y2.2 | length 790.6
  Top Layer w10: U4.23@3000.35,2573.05 3048.95,2573.05 v1(3052,2570) ; Y2.2@3480,2507.87 3584.63,2612.5 R23.2@3619.94,2612.5 3642.93,2589.5 3660.93,2607.5 C42.2@3680.06,2607.5
  Bottom Layer w10: v1(3052,2570) 3163.5,2570 3192,2598.5 3242.5,2598.5 3333.13,2507.87 Y2.2@3480,2507.87
NetC43_1: C43.1 U4.9 Y3.2 | length 651.1
  Top Layer w10: v1(2896,2230) 2893,2233 2893,2288 2902.46,2297.46 U4.9@3000.35,2297.46 ; Y3.2@3260,2116 3260,2141 3273,2154 C43.1@3273,2180
  Bottom Layer w10: v1(2896,2230) 3004,2122 3108,2122 3114,2116 Y3.2@3260,2116
NetC44_1: C44.1 U4.71 | length 175.7
  Top Layer w10: U4.71@2232.64,2927.38 2232.64,2958.5 2232.5,2958.64 2232.5,3008.86 2240,3016.36 C44.1@2240,3099.94
NetC45_1: C45.1 U4.106 | length 211.4
  Top Layer w10: C45.1@1919.94,2220 2008.68,2220 2049.33,2179.35 U4.106@2114.53,2179.35
NetC64_1: C64.1 U5.1 | length 89.2
  Top Layer w10: C64.1@4860,2567 4888,2595 U5.1@4937.64,2595
NetC64_2: C64.2 U5.3 | length 85
  Top Layer w10: C64.2@4859.94,2512.5 4890,2512.5 4907.5,2495 U5.3@4937.64,2495
NetC66_2: C66.2 U5.2 | length 192.9
  Top Layer w10: C66.2@4932.5,2660.06 4966.56,2626 4984,2626 4994,2616 4994,2569.25 4969.75,2545 U5.2@4937.64,2545
NetC67_1: C67.1 U5.5 | length 85.1
  Top Layer w10: C67.1@4860,2413 4878,2395 U5.5@4937.64,2395
NetC67_2: C67.2 U5.4 | length 86.9
  Top Layer w10: C67.2@4860.06,2467.5 4882.56,2445 U5.4@4937.64,2445
NetC68_2: C68.2 U5.6 | length 917.3
  Top Layer w10: U5.6@4937.64,2345 4906,2345 4906,2362 4853.5,2362 4843.5,2352 4843.5,2209.5 4886,2167 4984,2167 5050,2233 5050,2456 5064,2470 5197.44,2470 C68.2@5219.94,2492.5
NetC73_2: C73.2 C74.2 R49.1 U8.8 U8.13 | length 437.6
  Top Layer w9.84: 4842.18,1829.53 U8.8@4877.28,1829.53 4935.47,1829.53 ; U8.13@4910.79,1717.28 4910.79,1738.79 4940,1768
  Top Layer w10: R49.1@4640,1867 4669,1867 4669.5,1867.5 C73.2@4700.06,1867.5 C74.2@4760.06,1867.5 4804.21,1867.5 4842.18,1829.53 ; 4935.47,1829.53 4940,1825 4940,1768
NetC76_2: C76.2 U8.20 | length 98.6
  Top Layer w9.84: U8.20@5042.72,1770.47 5089,1770.47
  Top Layer w10: 5089,1770.47 5091.97,1767.5 C76.2@5140.06,1767.5
NetC77_2: C77.2 U8.10 | length 212.8
  Top Layer w9.84: v1(4831.68,1790.16) U8.10@4877.28,1790.16
  Top Layer w10: C77.2@4747.5,1699.94 v1(4774,1699.94)
  Bottom Layer w10: v1(4774,1699.94) 4785.13,1711.06 4785.13,1784 4794.84,1793.71 4828.13,1793.71 v1(4831.68,1790.16)
NetC80_2: C80.2 MOS1.3 USB_HOST.1 | length 803.1
  Top Layer w10: USB_HOST.1@504.09,1526.3 549.13,1571.34 549.13,1697.07 547.5,1698.71 C80.2@547.5,1719.94 ; MOS1.3@900,1410.79 v1(958,1410.79)
  Bottom Layer w10: USB_HOST.1@504.09,1526.3 540.79,1563 805.79,1563 v1(958,1410.79)
NetC83_1: C83.1 U15.1 | length 95.4
  Top Layer w10: U15.1@5471,3746 5506.11,3781.11 5506.11,3820 C83.1@5513,3820
NetC83_2: C83.2 D3.2 L2.2 U15.6 | length 817.8
  Top Layer w10: L2.2@5470,3460 5470,3535 5406,3535 5373,3568 5373,3755 5485,3867 5521,3867 5567.78,3820.22 5588,3800 ; U15.6@5571,3746 5571,3781 5567.5,3784.5 C83.2@5567.5,3819.94 5588,3800 ; D3.2@5640,3800 5588,3800
NetC89_2: C89.2 C90.2 D4.2 R68.1 U15.5 | length 846.2
  Top Layer w10: R68.1@5420,3687 5420,3755 5457,3792 v1(5483,3792) ; v1(5527,3708.6) U15.5@5571,3708.6 5647,3708.6 5686.2,3747.8 5720,3747.8 D4.2@5720,3780 ; C89.2@5787.5,3699.94 5787.5,3760.5 5768,3780 ; C90.2@5907.5,3699.94 5827.44,3780 5768,3780 ; D4.2@5720,3780 5768,3780 ; D4.2@5720,3780 5768,3780
  Bottom Layer w10: v1(5483,3792) 5483,3752.6 v1(5527,3708.6)
NetC93_2: C93.2 U17.4 | length 132.9
  Top Layer w10: C93.2@667.5,659.94 713.97,659.94 735,680.97 U17.4@735,737.64
NetC98_2: C98.2 U17.7 Y4.1 | length 680.7
  Top Layer w10: U17.7@885,737.64 v1(885,793) ; Y4.1@1140,900 1140,843.5 1154.5,829 C98.2@1154.5,773.06
  Bottom Layer w10: v1(885,793) 1060,793 1077,776 1077,734 1099,712 1125,712 1140,727 Y4.1@1140,900
NetC99_2: C99.2 U17.8 Y4.2 | length 728.3
  Top Layer w10: U17.8@935,737.64 935,737 996,737 1083,824 1083,920 1101,938 1160,938 1178,920 1178,869.56 C99.2@1274.5,773.06 1274.5,842.37 Y4.2@1332.13,900
NetCAN_1: CAN.1 R51.2 U10.7 | length 964.6
  Top Layer w10: v1(417,3904) 417,3739.06 456,3700.06 R51.2@472.5,3700.06 472.5,3662.5 470,3660 U10.7@470,3624.41
  Bottom Layer w10: CAN.1@380,4540 417,4503 v1(417,3904)
NetCAN_2: CAN.2 R51.1 U10.6 | length 1583.1
  Top Layer w10: U10.6@520,3624.41 520,3658 527,3665 R51.1@527,3700 443,3784 443,4115 335,4115 262,4042 152,4042 143,4051 143,4104 163,4124 252,4124 576.85,4448.85 CAN.2@576.85,4540
NetCOM2_2: COM2.2 U5.14 | length 5659.3
  Top Layer w10: v1(1747,3133) v1(1747,4184) ; v1(5047.62,2518.68) 5071.3,2495 U5.14@5142.36,2495
  Bottom Layer w10: COM2.2@1211,4280 1211,4216 1243,4184 v1(1747,4184) ; v1(1747,3133) 2037.44,2842.56 2060.58,2842.56 2241.64,2661.5 2388.59,2661.5 2792.02,2258.07 2825.06,2258.07 2829.63,2253.5 2940.11,2253.5 3039.61,2154 3255,2154 3276,2175 3668,2175 3687,2156 4353,2156 4442,2245 4804,2245 5025.5,2466.5 5025.5,2496.56 v1(5047.62,2518.68)
NetCOM2_3: COM2.3 U5.13 | length 8027.7
  Top Layer w10: v1(1044,1972) 1044,3702 1290,3948 v1(1290,4225) ; v1(1294,1216) v1(1294,1722) ; v1(2665,1631.5) 2665,1769 v1(2681,1785) ; v1(4086,1864) 4086,1912 4119,1945 4168,1945 4190,1923 4190,1880 4214,1856 v1(4369.99,1856) ; v1(5086.15,2445) U5.13@5142.36,2445
  Bottom Layer w10: v1(1044,1972) v1(1294,1722) ; v1(1290,4225) 1320,4233 COM2.3@1320,4280 ; v1(1294,1216) 2034,1216 2449.5,1631.5 v1(2665,1631.5) ; v1(2681,1785) 2717.5,1748.5 3263.5,1748.5 3375.4,1860.4 4082.4,1860.4 v1(4086,1864) ; v1(4369.99,1856) 4498.99,1985 4865,1985 5086.15,2206.15 v1(5086.15,2445)
NetD0_1: D0.1 R41.1 | length 72.9
  Top Layer w10: D0.1@3719.97,60.06 3719.97,96 ; 3720,96.03 R41.1@3720,133
NetD1_1: D1.1 R46.1 | length 72.9
  Top Layer w10: D1.1@3519.97,60.06 3519.97,96 ; 3520,96.03 R46.1@3520,133
NetD4_1: D4.1 DC_IN.1 | length 238.7
  Top Layer w10: D4.1@5720,3920 5720,4035 5740.91,4055.91 DC_IN.1@5740.91,4150
NetD7_2: D7.2 Q3.3 R70.1 | length 277
  Top Layer w10: Q3.3@780,1068.74 935.74,1068.74 R70.1@960,1093 960,1100 D7.2@1040,1100
NetEARTHNET_10: EARTHNET.10 R18.2 | length 1036.8
  Top Layer w10: R18.2@4800.06,4067.5 4800.06,4210.06 4891,4301 4891,4504 4926,4539 5373.91,4539 EARTHNET.10@5420,4492.91
NetEARTHNET_11: EARTHNET.11 R19.2 | length 496.5
  Top Layer w10: R19.2@4880.06,4087.5 4880.06,4255 4929,4303.94 4929,4321.91 EARTHNET.11@5100,4492.91
NetLS_2: LS.2 R58.1 R60.2 | length 188.1
  Top Layer w10: R60.2@1437.5,169.94 1470,169.94 1470.06,170 R58.1@1503,170 1503,111.96 1497.04,106 LS.2@1497.04,49.94
NetMOS1_1: MOS1.1 R54.2 | length 83.9
  Top Layer w10: MOS1.1@937.4,1509.21 977,1509.21 980.29,1512.5 R54.2@1019.94,1512.5
NetP1_1: P1.1 SP+.1 U2.23 | length 3991.5
  Top Layer w9.84: v1(4904.33,1320.21) 4913.76,1310.79 U2.23@4937.59,1310.79
  Bottom Layer w10: SP+.1@2720,1140 3301,1140 3318.5,1157.5 3924.44,1157.5 3948.9,1133.04 4041,1133.04 4058.96,1151 4263,1151 4350.88,1238.88 4904.33,1238.88 4979.27,1313.82 ; v1(4904.33,1320.21) 4910.72,1313.82 4979.27,1313.82 ; P1.1@6240,1080 6240,1305 6217.26,1327.74 5280.49,1327.74 5266.57,1313.82 5124.37,1313.82 5097.81,1287.26 5076.68,1287.26 5074.43,1285 5041.06,1285 5040.56,1284.5 5019.44,1284.5 4990.11,1313.82 4979.27,1313.82
NetP1_2: P1.2 SP-.1 U2.25 | length 3911.7
  Top Layer w9.84: v1(4940,1235) 4971.1,1235 U2.25@4971.1,1257.59
  Bottom Layer w10: SP-.1@2720,1000 3187,1000 3326.5,1139.5 3345.5,1139.5 3450.14,1034.86 4739.86,1034.86 v1(4940,1235) 4970,1265 5010.48,1265 5011.98,1266.5 5102.51,1266.5 5129.43,1293.42 5605.58,1293.42 5919,980 P1.2@6240,980
NetP11_5: P11.5 R53.1 | length 1026.5
  Top Layer w10: R53.1@227,1300 227,1784 259,1816 496,1816 P11.5@680,2000
NetP11_6: P11.6 R52.1 | length 967.3
  Top Layer w10: R52.1@293,1300 293,1625 452,1784 564,1784 P11.6@780,2000
NetPWR_1: PWR.1 R47.1 | length 83
  Top Layer w10: R47.1@6120,313 6156,313 6163.03,320.03 PWR.1@6200.06,320.03
NetQ1_2: Q1.2 R59.2 R61.2 | length 137.4
  Top Layer w10: R59.2@1842.94,528.5 1865,528.5 1880,543.5 R61.2@1903.06,543.5 1932.97,573.4 Q1.2@1961.74,573.4
NetQ2_2: Q2.2 R57.2 | length 95.6
  Top Layer w10: Q2.2@897.4,1801.26 944,1801.26 945.2,1800.06 R57.2@992.5,1800.06
NetQ2_3: Q2.3 R54.1 R56.1 | length 266.6
  Top Layer w10: Q2.3@860,1708.74 R56.1@860,1627 960,1627 R54.1@1020,1567
NetQ3_1: Q3.1 R72.1 U17.14 | length 271.5
  Top Layer w10: U17.14@685,942.36 685,1018 R72.1@687,1020 666,1041 666,1104 723.26,1161.26 Q3.1@742.6,1161.26
NetQ3_2: Q3.2 R71.2 | length 662.2
  Top Layer w10: R71.2@807.5,1019.94 1050.94,1019.94 1079,1048 1079,1144 1044.5,1178.5 920.5,1178.5 903.26,1161.26 Q3.2@817.4,1161.26
NetQ4_2: Q4.2 R72.2 | length 62.8
  Top Layer w10: Q4.2@622.6,1078.74 622.6,1053.9 632.5,1044 R72.2@632.5,1020.06
NetQ4_3: Q4.3 R73.1 | length 72.1
  Top Layer w10: R73.1@633,1220 633,1177.53 639.27,1171.26 Q4.3@660,1171.26
NetR2_2: R2.2 U1.12 | length 611.1
  Top Layer w9.84: v1@4649.21,3288.79 U1.12@4649.21,3377.28
  Top Layer w10: v1@4649.21,3288.79 v1(4651,3287) ; R2.2@5002.5,3425.94 5049.06,3425.94 v1(5058,3417)
  Bottom Layer w10: v1(4651,3287) 4803,3287 4848,3332 4973,3332 v1(5058,3417)
NetR11_2: R11.2 U1.24 | length 1138.5
  Top Layer w9.84: U1.24@4550.79,3542.72 4550.79,3853.79
  Top Layer w10: 4550.79,3853.79 4639,3942 4664,3942 4685,3913 4637,3865 4637,3816 4653,3800 4718,3800 4750,3832 4760,3876 4856,3876 4913.5,3818.5 4913.5,3762.5 4857.5,3706.5 R11.2@4823.06,3706.5
NetR15_2: R15.2 U2.18 | length 305.2
  Top Layer w9.84: 4718.22,1409.21 U2.18@4937.59,1409.21
  Top Layer w10: R15.2@4657.5,1469.94 4718.22,1409.21
NetR26_1: R26.1 R27.1 U4.143 | length 458.1
  Top Layer w10: v1(2703.74,1836.74) R27.1@2727,1860 ; v1(2823,1788) 2847,1812 R26.1@2847,1860 2891.5,1904.5 2891.5,1958.94 2882.24,1968.2 U4.143@2882.24,2041.55
  Bottom Layer w10: v1(2703.74,1836.74) 2704.06,1836.42 2774.58,1836.42 v1(2823,1788)
NetR37_2: R37.2 U6.8 | length 225.5
  Top Layer w10: U6.8@80,4380 127,4333 222,4333 236.5,4347.5 R37.2@280.06,4347.5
